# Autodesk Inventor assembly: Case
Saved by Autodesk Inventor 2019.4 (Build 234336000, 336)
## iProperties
Created: 2020-01
Part Number: Case
Document SubType Name: Assembly
Designer: Administrator
Title: Case v15
Author: Administrator
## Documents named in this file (5)
- c:\worker\convert-fusion-r01\tmp\job-1\133\output\files\da311742-6a18-4413-9c1a-65dbd131a173\b9f25881-16f9-4b54-b373-6705c0317c40.iam
- c:\worker\convert-fusion-r01\tmp\job-1\133\output\files\da311742-6a18-4413-9c1a-65dbd131a173\Sterownik v3.ipt
- c:\worker\convert-fusion-r01\tmp\job-1\133\output\files\da311742-6a18-4413-9c1a-65dbd131a173\Wspornik v1.ipt
- c:\worker\convert-fusion-r01\tmp\job-1\133\output\files\da311742-6a18-4413-9c1a-65dbd131a173\Prowadnica v6.iam
- c:\worker\convert-fusion-r01\tmp\job-1\133\output\files\da311742-6a18-4413-9c1a-65dbd131a173\Case v15.ipt
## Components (4 placed, 4 different names)
1. Sterownik v3:1
2. Wspornik v1:1
3. Prowadnica v6:1 [sub-assembly]
4. Case v15
